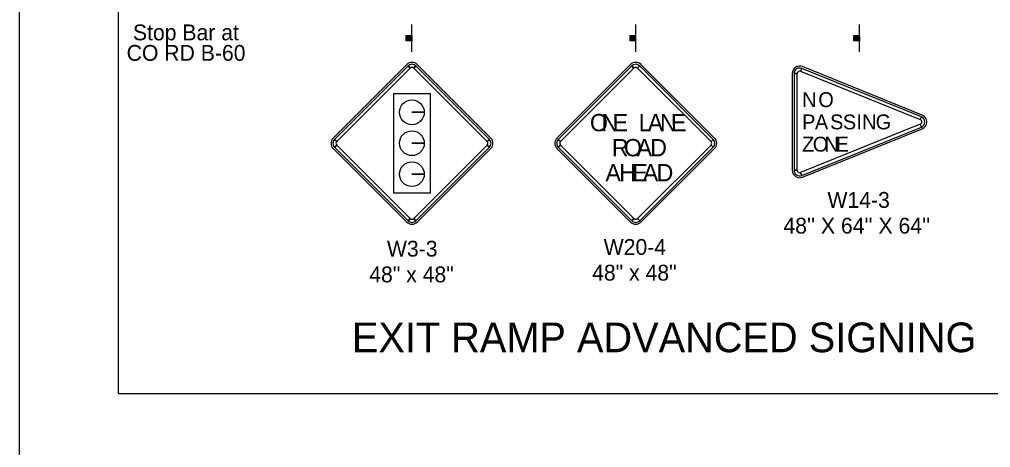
# Model space of a CAD drawing. Extents: x -2134934 to -2122394, y -2139046 to -2137036.
# Drawn here: x -2125529 to -2124549, y -2138041 to -2137608 of the extents above; entities that cross this region are included whole.
import ezdxf

# ---------------------------------------------------------------- set-up
doc = ezdxf.new("R2010")
doc.units = 0
for name, color, linetype in [('Barrier', 7, 'Continuous'), ('BridgeSuperStructureExisting', 7, 'Continuous'), ('Default', 7, 'Continuous')]:
    doc.layers.add(name, color=color, linetype=linetype)

msp = doc.modelspace()

# ---------------------------------------------------------------- linework, layer by layer
at = {"layer": 'Barrier'}
for p, q in [((-2125138.25, -2137653.96), (-2125212.49, -2137728.2)), ((-2125136.92, -2137655.28), (-2125134.71, -2137657.49)), ((-2125131.18, -2137657.49), (-2125128.97, -2137655.28)), ((-2125053.4, -2137728.2), (-2125127.64, -2137653.96)), ((-2124912.21, -2137653.96), (-2124986.46, -2137728.2)), ((-2124910.89, -2137655.28), (-2124908.68, -2137657.49)), ((-2124905.14, -2137657.49), (-2124902.93, -2137655.28)), ((-2124827.36, -2137728.2), (-2124901.61, -2137653.96)), ((-2124748.78, -2137663.01), (-2124748.78, -2137760.76)), ((-2124746.91, -2137663.01), (-2124743.78, -2137663.01)), ((-2124740.35, -2137660.69), (-2124739.17, -2137657.79)), ((-2124617.65, -2137704.93), (-2124738.47, -2137656.05)), ((-2125120.54, -2137702.18), (-2125133.04, -2137702.18)), ((-2125133.04, -2137702.18), (-2125120.54, -2137702.18)), ((-2124618.35, -2137706.67), (-2124619.52, -2137709.57)), ((-2124619.52, -2137714.2), (-2124618.35, -2137717.1)), ((-2124738.47, -2137767.71), (-2124617.65, -2137718.84)), ((-2125208.96, -2137731.74), (-2125211.17, -2137729.53)), ((-2125120.54, -2137733.43), (-2125133.04, -2137733.43)), ((-2125133.04, -2137733.43), (-2125120.54, -2137733.43)), ((-2125054.72, -2137729.53), (-2125056.93, -2137731.74)), ((-2124982.92, -2137731.74), (-2124985.13, -2137729.53)), ((-2124828.69, -2137729.53), (-2124830.89, -2137731.74)), ((-2125212.49, -2137738.81), (-2125138.25, -2137813.06)), ((-2125211.17, -2137737.48), (-2125208.96, -2137735.27)), ((-2125127.64, -2137813.06), (-2125053.4, -2137738.81)), ((-2125056.93, -2137735.27), (-2125054.72, -2137737.48)), ((-2124986.46, -2137738.81), (-2124912.21, -2137813.06)), ((-2124985.13, -2137737.49), (-2124982.92, -2137735.28)), ((-2124901.61, -2137813.06), (-2124827.36, -2137738.81)), ((-2124830.89, -2137735.28), (-2124828.69, -2137737.49)), ((-2124743.78, -2137760.76), (-2124746.91, -2137760.76)), ((-2124739.17, -2137765.97), (-2124740.35, -2137763.08)), ((-2125120.54, -2137764.68), (-2125133.04, -2137764.68)), ((-2125133.04, -2137764.68), (-2125120.54, -2137764.68)), ((-2125134.71, -2137809.52), (-2125136.92, -2137811.73)), ((-2125128.97, -2137811.73), (-2125131.18, -2137809.52)), ((-2124908.68, -2137809.52), (-2124910.89, -2137811.73)), ((-2124902.93, -2137811.73), (-2124905.14, -2137809.52))]:
    msp.add_line(p, q, dxfattribs=at)
for points in [[(-2125429.46, -2137135.95), (-2124308.22, -2137135.95), (-2124308.22, -2137986.59), (-2125429.46, -2137986.59)], [(-2125136.92, -2137655.28), (-2125211.17, -2137729.53), (-2125208.96, -2137731.74), (-2125134.71, -2137657.49), (-2125136.92, -2137655.28)], [(-2125054.72, -2137729.53), (-2125128.97, -2137655.28), (-2125131.18, -2137657.49), (-2125056.93, -2137731.74), (-2125054.72, -2137729.53)], [(-2124910.89, -2137655.28), (-2124985.13, -2137729.53), (-2124982.92, -2137731.74), (-2124908.68, -2137657.49), (-2124910.89, -2137655.28)], [(-2124828.69, -2137729.53), (-2124902.93, -2137655.28), (-2124905.14, -2137657.49), (-2124830.89, -2137731.74), (-2124828.69, -2137729.53)], [(-2124746.91, -2137663.01), (-2124746.91, -2137760.76), (-2124743.78, -2137760.76), (-2124743.78, -2137663.01), (-2124746.91, -2137663.01)], [(-2124618.35, -2137706.67), (-2124739.17, -2137657.79), (-2124740.35, -2137660.69), (-2124619.52, -2137709.57), (-2124618.35, -2137706.67)], [(-2125114.21, -2137683.56), (-2125151.68, -2137683.56), (-2125151.68, -2137783.45), (-2125114.21, -2137783.45), (-2125114.21, -2137683.56)], [(-2124739.17, -2137765.97), (-2124618.35, -2137717.1), (-2124619.52, -2137714.2), (-2124740.35, -2137763.08), (-2124739.17, -2137765.97)], [(-2125211.17, -2137737.48), (-2125136.92, -2137811.73), (-2125134.71, -2137809.52), (-2125208.96, -2137735.27), (-2125211.17, -2137737.48)], [(-2125128.97, -2137811.73), (-2125054.72, -2137737.48), (-2125056.93, -2137735.27), (-2125131.18, -2137809.52), (-2125128.97, -2137811.73)], [(-2124985.13, -2137737.49), (-2124910.89, -2137811.73), (-2124908.68, -2137809.52), (-2124982.92, -2137735.28), (-2124985.13, -2137737.49)], [(-2124902.93, -2137811.73), (-2124828.69, -2137737.49), (-2124830.89, -2137735.28), (-2124905.14, -2137809.52), (-2124902.93, -2137811.73)]]:
    msp.add_lwpolyline(points, close=True, dxfattribs=at)
for centre in [(-2125133.04, -2137702.18), (-2125133.04, -2137733.43), (-2125133.04, -2137764.68)]:
    msp.add_circle(centre, 12.5, dxfattribs=at)
for centre, radius, start, end in [((-2125132.94, -2137659.26), 7.5, 44.99999, 134.99974), ((-2125132.94, -2137659.26), 5.62, 44.99999, 134.99974), ((-2124906.91, -2137659.26), 7.5, 44.99999, 134.99974), ((-2124906.91, -2137659.26), 5.62, 44.99999, 134.99974), ((-2124741.28, -2137663.01), 7.5, 67.97571, 179.99985), ((-2125132.94, -2137659.26), 2.5, 44.99999, 134.99974), ((-2124906.91, -2137659.26), 2.5, 44.99999, 134.99974), ((-2124741.28, -2137663.01), 5.62, 67.97571, 179.99985), ((-2124741.28, -2137663.01), 2.5, 67.97571, 179.99985), ((-2124620.46, -2137711.88), 2.5, 292.02456, 67.97541), ((-2124620.46, -2137711.88), 5.62, 292.02456, 67.97541), ((-2124620.46, -2137711.88), 7.5, 292.02456, 67.97598), ((-2125207.19, -2137733.51), 7.5, 134.99974, 224.99995), ((-2125207.19, -2137733.51), 5.62, 134.99974, 224.99995), ((-2125207.19, -2137733.51), 2.5, 134.99974, 224.99995), ((-2125058.7, -2137733.51), 2.5, 315.00016, 44.9998), ((-2125058.7, -2137733.51), 5.62, 315.00016, 44.9998), ((-2125058.7, -2137733.51), 7.5, 315.00016, 44.9998), ((-2124981.15, -2137733.51), 7.5, 134.99974, 224.99995), ((-2124981.15, -2137733.51), 5.62, 134.99974, 224.99995), ((-2124981.15, -2137733.51), 2.5, 134.99974, 224.99995), ((-2124832.66, -2137733.51), 2.5, 315.00016, 44.9998), ((-2124832.66, -2137733.51), 5.62, 315.00016, 44.9998), ((-2124832.66, -2137733.51), 7.5, 315.00016, 44.9998), ((-2124741.28, -2137760.76), 7.5, 179.99985, 292.02456), ((-2124741.28, -2137760.76), 5.62, 179.99985, 292.02456), ((-2124741.28, -2137760.76), 2.5, 179.99985, 292.02456), ((-2125132.94, -2137807.75), 5.62, 224.99995, 315.00016), ((-2125132.94, -2137807.75), 2.5, 224.99995, 315.00016), ((-2124906.91, -2137807.75), 5.62, 224.99995, 315.00016), ((-2124906.91, -2137807.75), 2.5, 224.99995, 315.00016), ((-2125132.94, -2137807.75), 7.5, 224.99995, 315.00016), ((-2124906.91, -2137807.75), 7.5, 224.99995, 315.00016)]:
    msp.add_arc(centre, radius, start, end, dxfattribs=at)
at = {"layer": 'BridgeSuperStructureExisting'}
for p, q in [((-2125132.94, -2137640.94), (-2125132.94, -2137613.44)), ((-2124906.91, -2137640.94), (-2124906.91, -2137613.44)), ((-2124680.87, -2137640.94), (-2124680.87, -2137613.44)), ((-2125138.27, -2137630.08), (-2125138.27, -2137624.49)), ((-2125137.95, -2137624.49), (-2125137.95, -2137630.08)), ((-2125137.73, -2137630.08), (-2125137.73, -2137624.49)), ((-2125137.41, -2137624.49), (-2125137.41, -2137630.08)), ((-2125137.18, -2137630.08), (-2125137.2, -2137624.49)), ((-2125136.77, -2137624.49), (-2125136.75, -2137630.08)), ((-2125136.55, -2137630.08), (-2125136.55, -2137624.49)), ((-2125136.11, -2137624.49), (-2125136.11, -2137630.08)), ((-2125135.74, -2137630.08), (-2125135.74, -2137624.49)), ((-2125135.42, -2137624.49), (-2125135.4, -2137630.08)), ((-2125135.2, -2137630.08), (-2125135.2, -2137624.49)), ((-2125134.93, -2137624.49), (-2125134.93, -2137630.08)), ((-2125134.6, -2137630.08), (-2125134.6, -2137624.49)), ((-2125134.39, -2137624.49), (-2125134.39, -2137630.08)), ((-2125134.16, -2137630.08), (-2125134.16, -2137624.49)), ((-2125133.9, -2137624.49), (-2125133.9, -2137630.08)), ((-2125133.64, -2137630.08), (-2125133.64, -2137624.49)), ((-2125133.36, -2137624.49), (-2125133.36, -2137630.08)), ((-2124912.23, -2137630.08), (-2124912.23, -2137624.49)), ((-2124911.92, -2137624.49), (-2124911.92, -2137630.08)), ((-2124911.69, -2137630.08), (-2124911.69, -2137624.49)), ((-2124911.37, -2137624.49), (-2124911.37, -2137630.08)), ((-2124911.15, -2137630.08), (-2124911.17, -2137624.49)), ((-2124910.73, -2137624.49), (-2124910.72, -2137630.08)), ((-2124910.51, -2137630.08), (-2124910.51, -2137624.49)), ((-2124910.08, -2137624.49), (-2124910.08, -2137630.08)), ((-2124909.7, -2137630.08), (-2124909.7, -2137624.49)), ((-2124909.38, -2137624.49), (-2124909.37, -2137630.08)), ((-2124909.16, -2137630.08), (-2124909.16, -2137624.49)), ((-2124908.9, -2137624.49), (-2124908.9, -2137630.08)), ((-2124908.56, -2137630.08), (-2124908.56, -2137624.49)), ((-2124908.35, -2137624.49), (-2124908.35, -2137630.08)), ((-2124908.13, -2137630.08), (-2124908.13, -2137624.49)), ((-2124907.87, -2137624.49), (-2124907.87, -2137630.08)), ((-2124907.6, -2137630.08), (-2124907.6, -2137624.49)), ((-2124907.32, -2137624.49), (-2124907.32, -2137630.08)), ((-2124686.2, -2137630.08), (-2124686.2, -2137624.49)), ((-2124685.88, -2137624.49), (-2124685.88, -2137630.08)), ((-2124685.65, -2137630.08), (-2124685.65, -2137624.49)), ((-2124685.34, -2137624.49), (-2124685.34, -2137630.08)), ((-2124685.11, -2137630.08), (-2124685.13, -2137624.49)), ((-2124684.7, -2137624.49), (-2124684.68, -2137630.08)), ((-2124684.47, -2137630.08), (-2124684.47, -2137624.49)), ((-2124684.04, -2137624.49), (-2124684.04, -2137630.08)), ((-2124683.67, -2137630.08), (-2124683.67, -2137624.49)), ((-2124683.35, -2137624.49), (-2124683.33, -2137630.08)), ((-2124683.12, -2137630.08), (-2124683.12, -2137624.49)), ((-2124682.86, -2137624.49), (-2124682.86, -2137630.08)), ((-2124682.52, -2137630.08), (-2124682.52, -2137624.49)), ((-2124682.32, -2137624.49), (-2124682.32, -2137630.08)), ((-2124682.09, -2137630.08), (-2124682.09, -2137624.49)), ((-2124681.83, -2137624.49), (-2124681.83, -2137630.08)), ((-2124681.57, -2137630.08), (-2124681.57, -2137624.49)), ((-2124681.29, -2137624.49), (-2124681.29, -2137630.08))]:
    msp.add_line(p, q, dxfattribs=at)
for points in [[(-2125133.04, -2137624.49), (-2125133.04, -2137630.12), (-2125138.66, -2137630.12), (-2125138.66, -2137624.49)], [(-2124907, -2137624.49), (-2124907, -2137630.12), (-2124912.63, -2137630.12), (-2124912.63, -2137624.49)], [(-2124680.97, -2137624.49), (-2124680.97, -2137630.12), (-2124686.59, -2137630.12), (-2124686.59, -2137624.49)]]:
    msp.add_lwpolyline(points, close=True, dxfattribs=at)
at = {"layer": 'Default'}
msp.add_lwpolyline([(-2125529.46, -2137035.95), (-2122394.47, -2137035.95), (-2122394.47, -2139045.94), (-2125529.46, -2139045.94)], close=True, dxfattribs=at)

# ---------------------------------------------------------------- texts
at = {"layer": 'Barrier'}
for s, height, p in [('N', 15, (-2124738.82, -2137696.88)), ('O', 15, (-2124722.48, -2137696.88)), ('O', 17.5, (-2124953.19, -2137721.32)), ('N', 17.5, (-2124941.42, -2137721.32)), ('E', 17.5, (-2124930.19, -2137721.32)), ('L', 17.5, (-2124903.94, -2137721.32)), ('A', 17.5, (-2124894.74, -2137721.32)), ('N', 17.5, (-2124882.48, -2137721.32)), ('E', 17.5, (-2124871.25, -2137721.32)), ('P', 15, (-2124738.82, -2137719.38)), ('A', 15, (-2124725.92, -2137719.38)), ('S', 15, (-2124710.57, -2137719.38)), ('S', 15, (-2124697.68, -2137719.38)), ('I', 15, (-2124684.09, -2137719.38)), ('N', 15, (-2124678.23, -2137719.38)), ('G', 15, (-2124664.63, -2137719.38)), ('R', 17.5, (-2124931.09, -2137746.63)), ('O', 17.5, (-2124918.8, -2137746.63)), ('A', 17.5, (-2124905.96, -2137746.63)), ('D', 17.5, (-2124892.3, -2137746.63)), ('Z', 15, (-2124738.82, -2137741.88)), ('O', 15, (-2124728.08, -2137741.88)), ('N', 15, (-2124716.25, -2137741.88)), ('E', 15, (-2124704.89, -2137741.88)), ('A', 17.5, (-2124937.52, -2137771.95)), ('H', 17.5, (-2124923.66, -2137771.95)), ('E', 17.5, (-2124910.44, -2137771.95)), ('A', 17.5, (-2124899.73, -2137771.95)), ('D', 17.5, (-2124885.86, -2137771.95)), ('W14-3', 16, (-2124713.27, -2137798.71)), ("48'' X 64'' X 64''", 16, (-2124757.76, -2137824.71)), ('W3-3', 16, (-2125158.24, -2137847.97)), ('W20-4', 16, (-2124939.27, -2137846.25)), ('48" x 48"', 16, (-2125176.11, -2137873.97)), ('48" x 48"', 16, (-2124950.98, -2137872.25)), ('EXIT RAMP ADVANCED SIGNING', 30, (-2125193.65, -2137944.59))]:
    msp.add_text(s, height=height, dxfattribs=at).set_placement(p)
at = {"layer": 'BridgeSuperStructureExisting'}
for s, p in [('Stop Bar at', (-2125414.8, -2137629.44)), ('CO RD B-60', (-2125421.17, -2137650.15))]:
    msp.add_text(s, height=16, dxfattribs=at).set_placement(p)

doc.saveas('drawing.dxf')
